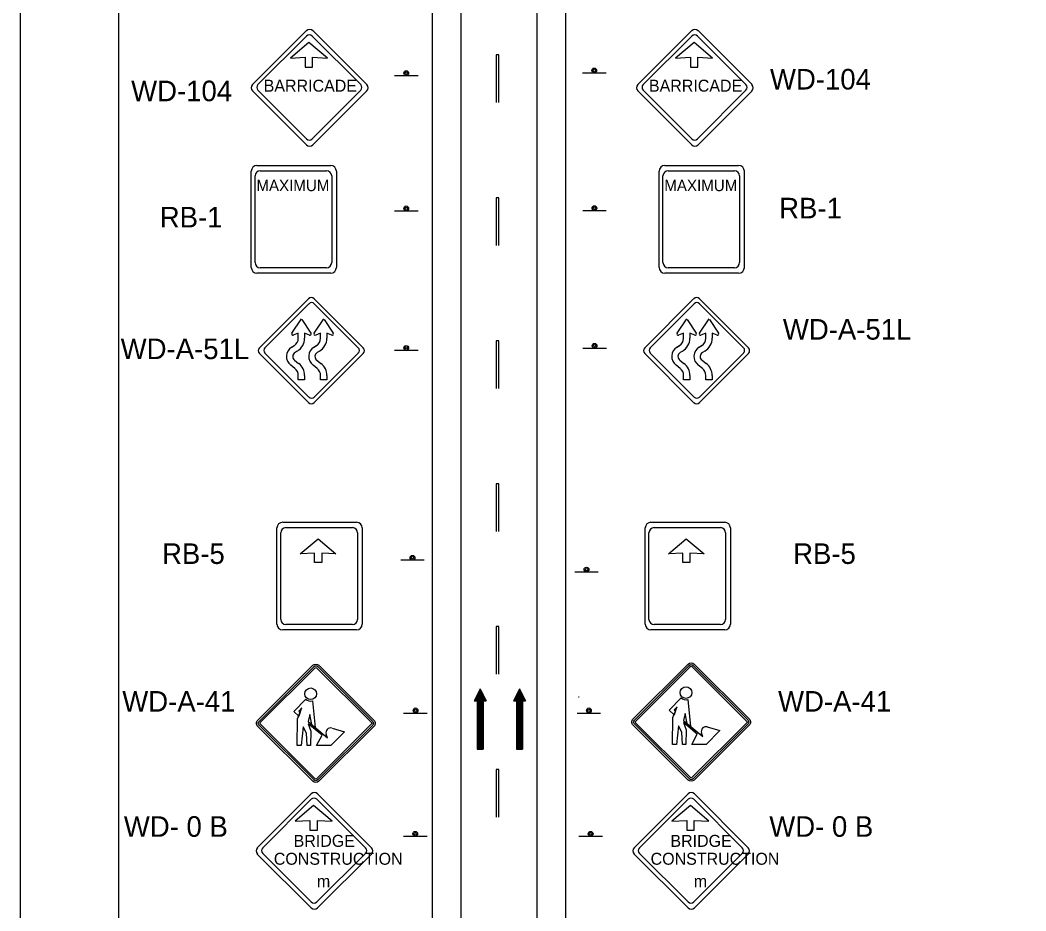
# Model space of a CAD drawing. Extents: x 2171 to 2395, y 134 to 413.
# Drawn here: x 2178.7 to 2280.9, y 183.7 to 274.1 of the extents above; entities that cross this region are included whole.
import ezdxf

# ---------------------------------------------------------------- set-up
doc = ezdxf.new("R2010")
doc.units = 0
for name, color, linetype in [('Level 1', 7, 'Continuous'), ('Level 10', 7, 'Continuous'), ('Level 2', 7, 'Continuous'), ('Level 20', 7, 'Continuous'), ('Level 44', 7, 'Continuous'), ('Level 60', 7, 'Continuous')]:
    doc.layers.add(name, color=color, linetype=linetype)

# ---------------------------------------------------------------- blocks, each defined once
blk = doc.blocks.new('2_95')
at = {"layer": 'Level 1'}
for points in [[(18.2, 120), (22.8, 116.1), (17.3, 102.4), (0, 118.7), (41.6, 161.6)], [(18.2, 120), (22.8, 116.1), (17.3, 102.4), (0, 118.7), (41.6, 161.6)], [(32.4, 65), (26.3, 0), (11.7, 0), (13.7, 93.4), (17.3, 102.4), (0, 118.7), (41.6, 161.6)], [(65.4, 155.5), (75, 62.5), (62.7, 72.8), (55.6, 107.4), (49.8, 83.3), (117.8, 27.3), (113.1, 39.4)], [(65.4, 155.5), (75, 62.5), (62.7, 72.8), (55.6, 107.4), (49.8, 83.3), (117.8, 27.3), (113.1, 39.4)], [(65.4, 155.5), (75, 62.5), (117.8, 27.3), (113.1, 39.4)], [(132.9, 60.9), (176.6, 47.8), (129.3, 0), (79.5, 0), (98.2, 36), (49.8, 75.6), (59.3, 50.4), (58.1, 0), (46.2, 0), (44, 43), (32.4, 65), (26.3, 0), (11.7, 0), (13.7, 93.4), (28.7, 130.9), (18.2, 120)], [(132.9, 60.9), (176.6, 47.8), (129.3, 0), (79.5, 0), (98.2, 36), (49.8, 75.6), (59.3, 50.4), (58.1, 0), (46.2, 0), (44, 43), (32.4, 65), (26.3, 0), (11.7, 0), (13.7, 93.4), (28.7, 130.9), (18.2, 120)], [(132.9, 60.9), (176.6, 47.8), (129.3, 0), (79.5, 0), (98.2, 36), (49.8, 75.6), (59.3, 50.4), (58.1, 0), (46.2, 0), (44, 43), (32.4, 65)]]:
    blk.add_lwpolyline(points, dxfattribs=at)
for points in [[(18.2, 120), (22.8, 116.1), (28.7, 130.9)], [(62.7, 72.7), (55.6, 107.4), (49.8, 83.3)]]:
    blk.add_lwpolyline(points, close=True, dxfattribs=at)
blk.add_circle((58.9, 179.8), 20.2, dxfattribs=at)
blk.add_circle((58.9, 179.8), 20.2, dxfattribs=at)
blk.add_circle((58.9, 179.8), 20.2, dxfattribs=at)
for centre, radius, start, end in [((58.9, 179.8), 25.1, 226.3135, 284.9576), ((58.9, 179.8), 25.1, 226.3135, 284.9576), ((58.9, 179.8), 25.1, 226.3135, 284.9576), ((128.2, 45.3), 16.3, 73.381, 201.0999), ((128.2, 45.3), 16.3, 73.381, 201.0999), ((128.2, 45.3), 16.3, 73.381, 201.0999)]:
    blk.add_arc(centre, radius, start, end, dxfattribs=at)
blk = doc.blocks.new('WDA41')
at = {"layer": 'Level 1'}
for p, q in [((-6.55, 0.35), (-0.35, 6.54)), ((-6.41, 0.21), (-0.21, 6.4)), ((-6.27, 0.07), (-0.08, 6.27)), ((0.07, 6.27), (6.27, 0.08)), ((0.21, 6.41), (6.41, 0.21)), ((0.35, 6.54), (6.54, 0.35)), ((0.29, 3.83), (0.3, 3.83)), ((-0.35, -6.54), (-6.55, -0.35)), ((-0.21, -6.4), (-6.41, -0.21)), ((-0.07, -6.27), (-6.27, -0.08)), ((6.27, -0.07), (0.08, -6.27)), ((6.41, -0.21), (0.21, -6.4)), ((6.55, -0.35), (0.35, -6.54))]:
    blk.add_line(p, q, dxfattribs=at)
for centre, radius, start, end in [((0, 6.19), 0.495, 45.0349, 135), ((0, 6.19), 0.3, 45.0349, 135), ((0, 6.19), 0.105, 45.0349, 135), ((-6.2, 0), 0.495, 135, 225.0349), ((-6.2, 0), 0.3, 135, 225.0349), ((-6.2, 0), 0.105, 135, 225.0349), ((6.2, 0), 0.105, 315, 45.035), ((6.2, 0), 0.3, 315, 45.035), ((6.2, 0), 0.495, 315, 45.035), ((0, -6.19), 0.495, 225.0348, 315), ((0, -6.19), 0.3, 225.0348, 315), ((0, -6.19), 0.105, 225.0348, 315)]:
    blk.add_arc(centre, radius, start, end, dxfattribs=at)
at = {"layer": 'Level 1', "xscale": 0.032498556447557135, "yscale": -0.032498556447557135, "rotation": 180}
blk.add_blockref('2_95', (2.5, -2.52), dxfattribs=at)

msp = doc.modelspace()

# ---------------------------------------------------------------- linework, layer by layer
at = {"layer": 'Level 10'}
for p, q in [((2223.52, 177.99), (2223.52, 287.5)), ((2231.26, 177.84), (2231.26, 284.77)), ((2206.34, 242.32), (2207.31, 243.78)), ((2207.35, 243.72), (2208.28, 242.32)), ((2208.6, 242.32), (2209.58, 243.78)), ((2209.62, 243.72), (2210.55, 242.32)), ((2245.46, 242.32), (2246.43, 243.78)), ((2246.47, 243.72), (2247.41, 242.32)), ((2247.72, 242.32), (2248.7, 243.78)), ((2248.74, 243.72), (2249.67, 242.32)), ((2206.99, 242.33), (2206.49, 242.13)), ((2206.99, 241.83), (2206.99, 242.33)), ((2208.13, 242.13), (2207.63, 242.33)), ((2207.63, 242.33), (2207.63, 241.83)), ((2209.26, 242.33), (2208.76, 242.13)), ((2209.26, 241.83), (2209.26, 242.33)), ((2210.4, 242.13), (2209.89, 242.33)), ((2209.89, 242.33), (2209.89, 241.83)), ((2246.11, 242.33), (2245.61, 242.13)), ((2246.11, 241.83), (2246.11, 242.33)), ((2247.25, 242.13), (2246.75, 242.33)), ((2246.75, 242.33), (2246.75, 241.83)), ((2248.38, 242.33), (2247.88, 242.13)), ((2248.38, 241.83), (2248.38, 242.33)), ((2249.52, 242.13), (2249.01, 242.33)), ((2249.01, 242.33), (2249.01, 241.83)), ((2206.33, 240.93), (2206.56, 241.07)), ((2208.59, 240.93), (2208.82, 241.07)), ((2245.45, 240.93), (2245.68, 241.07)), ((2247.71, 240.93), (2247.94, 241.07)), ((2206.89, 240.52), (2206.66, 240.38)), ((2209.15, 240.52), (2208.92, 240.38)), ((2246.01, 240.52), (2245.78, 240.38)), ((2248.27, 240.52), (2248.04, 240.38)), ((2206.64, 238.76), (2206.23, 239.08)), ((2206.62, 239.58), (2207.03, 239.26)), ((2208.91, 238.76), (2208.49, 239.08)), ((2208.88, 239.58), (2209.29, 239.26)), ((2245.76, 238.76), (2245.35, 239.08)), ((2245.74, 239.58), (2246.15, 239.26)), ((2248.03, 238.76), (2247.61, 239.08)), ((2248, 239.58), (2248.41, 239.26)), ((2206.99, 237.59), (2206.99, 238.04)), ((2207.63, 238.04), (2207.63, 237.59)), ((2209.26, 237.59), (2209.26, 238.04)), ((2209.89, 238.04), (2209.89, 237.59)), ((2246.11, 237.59), (2246.11, 238.04)), ((2246.75, 238.04), (2246.75, 237.59)), ((2248.38, 237.59), (2248.38, 238.04)), ((2249.01, 238.04), (2249.01, 237.59)), ((2225.47, 206.23), (2224.85, 205)), ((2225.01, 205.31), (2225.01, 205)), ((2225.08, 205.46), (2225.08, 205)), ((2225.16, 205.62), (2225.16, 200.09)), ((2225.24, 205.77), (2225.24, 200.09)), ((2225.31, 205.92), (2225.31, 200.09)), ((2225.39, 206.08), (2225.39, 200.09)), ((2225.47, 206.23), (2225.47, 200.09)), ((2225.47, 206.23), (2226.08, 205)), ((2225.54, 206.08), (2225.54, 200.09)), ((2225.62, 205.92), (2225.62, 200.09)), ((2225.7, 205.77), (2225.7, 200.09)), ((2225.77, 205.62), (2225.77, 200.09)), ((2225.85, 205.46), (2225.85, 205)), ((2225.93, 205.31), (2225.93, 205)), ((2229.45, 206.23), (2228.84, 205)), ((2228.99, 205.31), (2228.99, 205)), ((2229.07, 205.46), (2229.07, 205)), ((2229.14, 205.62), (2229.14, 200.09)), ((2229.22, 205.77), (2229.22, 200.09)), ((2229.3, 205.92), (2229.3, 200.09)), ((2229.38, 206.08), (2229.38, 200.09)), ((2229.45, 206.23), (2229.45, 200.09)), ((2229.45, 206.23), (2230.06, 205)), ((2229.53, 206.08), (2229.53, 200.09)), ((2229.6, 205.92), (2229.6, 200.09)), ((2229.68, 205.77), (2229.68, 200.09)), ((2229.76, 205.62), (2229.76, 200.09)), ((2229.83, 205.46), (2229.83, 205)), ((2229.91, 205.31), (2229.91, 205)), ((2224.85, 205), (2225.16, 205)), ((2224.93, 205.16), (2224.93, 205)), ((2225.16, 205), (2225.16, 200.09)), ((2225.77, 205), (2225.77, 200.09)), ((2225.77, 205), (2226.08, 205)), ((2226, 205.16), (2226, 205)), ((2228.84, 205), (2229.14, 205)), ((2228.91, 205.16), (2228.91, 205)), ((2229.14, 205), (2229.14, 200.09)), ((2229.76, 205), (2229.76, 200.09)), ((2229.76, 205), (2230.06, 205)), ((2229.99, 205.16), (2229.99, 205)), ((2225.16, 200.09), (2225.77, 200.09)), ((2229.14, 200.09), (2229.76, 200.09))]:
    msp.add_line(p, q, dxfattribs=at)
for points in [[(2207.63, 237.59), (2206.99, 237.59)], [(2209.89, 237.59), (2209.26, 237.59)], [(2246.75, 237.59), (2246.11, 237.59)], [(2249.01, 237.59), (2248.38, 237.59)]]:
    msp.add_lwpolyline(points, dxfattribs=at)
for centre, radius, start, end in [((2206.45, 242.25), 0.128, 146.2788, 291.7539), ((2208.18, 242.25), 0.128, 248.2461, 33.7212), ((2208.71, 242.25), 0.128, 146.2788, 291.7539), ((2210.44, 242.25), 0.128, 248.2461, 33.7212), ((2245.57, 242.25), 0.128, 146.2788, 291.7539), ((2247.3, 242.25), 0.128, 248.2461, 33.7212), ((2247.83, 242.25), 0.128, 146.2788, 291.7539), ((2249.56, 242.25), 0.128, 248.2461, 33.7212), ((2206.1, 241.83), 0.897, 301.2095, 0), ((2206.1, 241.83), 1.54, 301.2095, 0), ((2208.36, 241.83), 0.897, 301.2095, 0), ((2208.36, 241.83), 1.54, 301.2095, 0), ((2245.22, 241.83), 0.897, 301.2095, 0), ((2245.22, 241.83), 1.54, 301.2095, 0), ((2247.48, 241.83), 0.897, 301.2095, 0), ((2247.48, 241.83), 1.54, 301.2095, 0), ((2206.91, 239.97), 1.12, 121.1816, 232.5768), ((2206.91, 239.97), 0.483, 121.1644, 232.5768), ((2209.17, 239.97), 1.12, 121.1816, 232.5768), ((2209.17, 239.97), 0.483, 121.1644, 232.5768), ((2246.03, 239.97), 1.12, 121.1816, 232.5768), ((2246.03, 239.97), 0.483, 121.1644, 232.5768), ((2248.29, 239.97), 1.12, 121.1816, 232.5768), ((2248.29, 239.97), 0.483, 121.1644, 232.5768), ((2206.1, 238.04), 1.54, 0, 52.5572), ((2208.36, 238.04), 1.54, 0, 52.5572), ((2245.22, 238.04), 1.54, 0, 52.5572), ((2247.48, 238.04), 1.54, 0, 52.5572), ((2206.1, 238.04), 0.897, 0, 52.5572), ((2208.36, 238.04), 0.897, 0, 52.5572), ((2245.22, 238.04), 0.897, 0, 52.5572), ((2247.48, 238.04), 0.897, 0, 52.5572)]:
    msp.add_arc(centre, radius, start, end, dxfattribs=at)
at = {"layer": 'Level 2'}
for p, q in [((2227.07, 270.59), (2227.07, 265.75)), ((2227.36, 270.59), (2227.07, 270.59)), ((2227.36, 265.75), (2227.36, 270.59)), ((2227.07, 256.07), (2227.07, 251.24)), ((2227.36, 256.07), (2227.07, 256.07)), ((2227.36, 251.24), (2227.36, 256.07)), ((2227.07, 241.56), (2227.07, 236.72)), ((2227.36, 241.56), (2227.07, 241.56)), ((2227.36, 236.72), (2227.36, 241.56)), ((2227.07, 227.05), (2227.07, 222.21)), ((2227.36, 227.05), (2227.07, 227.05)), ((2227.36, 222.21), (2227.36, 227.05)), ((2227.07, 212.53), (2227.07, 207.69)), ((2227.36, 212.53), (2227.07, 212.53)), ((2227.36, 207.69), (2227.36, 212.53)), ((2227.07, 198.02), (2227.07, 193.18)), ((2227.36, 198.02), (2227.07, 198.02)), ((2227.36, 193.18), (2227.36, 198.02))]:
    msp.add_line(p, q, dxfattribs=at)
at = {"layer": 'Level 20'}
for p, q in [((2234.16, 177.84), (2234.16, 327.61)), ((2220.62, 177.82), (2220.62, 313.63))]:
    msp.add_line(p, q, dxfattribs=at)
at = {"layer": 'Level 44'}
for p, q in [((2207.83, 273.06), (2202.35, 267.59)), ((2213.95, 267.59), (2208.48, 273.06)), ((2246.95, 273.06), (2241.47, 267.59)), ((2253.07, 267.59), (2247.6, 273.06)), ((2202.9, 267.58), (2207.83, 272.5)), ((2208.07, 271.86), (2206.19, 270.27)), ((2209.95, 270.27), (2208.07, 271.86)), ((2208.41, 272.5), (2213.34, 267.58)), ((2242.02, 267.58), (2246.95, 272.5)), ((2247.19, 271.86), (2245.31, 270.27)), ((2249.07, 270.27), (2247.19, 271.86)), ((2247.53, 272.5), (2252.45, 267.58)), ((2206.19, 270.27), (2207.69, 270.35)), ((2207.69, 270.35), (2207.69, 269.35)), ((2208.45, 269.35), (2208.45, 270.35)), ((2208.45, 270.35), (2209.95, 270.27)), ((2245.31, 270.27), (2246.81, 270.35)), ((2246.81, 270.35), (2246.81, 269.35)), ((2247.57, 269.35), (2247.57, 270.35)), ((2247.57, 270.35), (2249.07, 270.27)), ((2207.69, 269.35), (2208.44, 269.35)), ((2238.24, 268.74), (2235.84, 268.74)), ((2246.81, 269.35), (2247.56, 269.35)), ((2219.15, 268.47), (2216.76, 268.47)), ((2202.35, 266.94), (2207.83, 261.46)), ((2202.36, 266.94), (2202.35, 266.94)), ((2207.83, 262.07), (2202.9, 267)), ((2213.34, 267), (2208.41, 262.07)), ((2208.48, 261.46), (2213.95, 266.94)), ((2241.47, 266.94), (2246.95, 261.46)), ((2241.47, 266.94), (2241.47, 266.94)), ((2246.95, 262.07), (2242.02, 267)), ((2252.45, 267), (2247.53, 262.07)), ((2247.6, 261.46), (2253.07, 266.94)), ((2202.22, 249.01), (2202.22, 258.78)), ((2202.8, 259.36), (2210.29, 259.36)), ((2203.12, 258.82), (2209.87, 258.82)), ((2210.87, 258.78), (2210.87, 249.01)), ((2243.63, 249.01), (2243.63, 258.78)), ((2244.21, 259.36), (2251.71, 259.36)), ((2244.54, 258.82), (2251.28, 258.82)), ((2252.28, 258.78), (2252.28, 249.01)), ((2202.6, 249.5), (2202.6, 258.3)), ((2210.39, 258.3), (2210.39, 249.5)), ((2244.02, 249.5), (2244.02, 258.3)), ((2251.8, 258.3), (2251.8, 249.5)), ((2219.15, 254.74), (2216.76, 254.74)), ((2238.26, 254.76), (2235.87, 254.76)), ((2202.6, 249.5), (2202.6, 249.5)), ((2244.02, 249.5), (2244.02, 249.5)), ((2202.22, 249.01), (2202.22, 249.01)), ((2210.29, 248.43), (2202.8, 248.43)), ((2209.87, 248.98), (2203.12, 248.98)), ((2243.63, 249.01), (2243.63, 249.01)), ((2251.71, 248.43), (2244.21, 248.43)), ((2251.28, 248.98), (2244.54, 248.98)), ((2203.05, 240.86), (2208.02, 245.83)), ((2208.08, 245.33), (2203.6, 240.85)), ((2208.61, 245.83), (2213.59, 240.86)), ((2213.09, 240.85), (2208.61, 245.33)), ((2242.17, 240.86), (2247.14, 245.83)), ((2247.2, 245.33), (2242.72, 240.85)), ((2247.73, 245.83), (2252.71, 240.86)), ((2252.21, 240.85), (2247.73, 245.33)), ((2208.02, 235.29), (2203.05, 240.27)), ((2203.6, 240.32), (2208.08, 235.84)), ((2208.61, 235.84), (2213.09, 240.32)), ((2213.59, 240.27), (2208.61, 235.29)), ((2213.59, 240.27), (2213.59, 240.27)), ((2219.15, 240.56), (2216.76, 240.56)), ((2238.29, 240.78), (2235.89, 240.78)), ((2247.14, 235.29), (2242.17, 240.27)), ((2242.72, 240.32), (2247.2, 235.84)), ((2247.73, 235.84), (2252.21, 240.32)), ((2252.71, 240.27), (2247.73, 235.29)), ((2252.7, 240.27), (2252.71, 240.27)), ((2205.41, 223.13), (2212.91, 223.13)), ((2242.79, 223.13), (2250.29, 223.13)), ((2204.83, 212.78), (2204.83, 222.55)), ((2205.22, 213.27), (2205.22, 222.07)), ((2205.74, 222.59), (2212.49, 222.59)), ((2213.01, 222.07), (2213.01, 213.27)), ((2213.49, 222.55), (2213.49, 212.78)), ((2242.22, 212.78), (2242.22, 222.55)), ((2242.6, 213.27), (2242.6, 222.07)), ((2243.12, 222.59), (2249.87, 222.59)), ((2250.39, 222.07), (2250.39, 213.27)), ((2250.87, 222.55), (2250.87, 212.78)), ((2219.79, 219.27), (2217.4, 219.27)), ((2237.46, 218.07), (2235.07, 218.07)), ((2204.83, 212.78), (2204.83, 212.78)), ((2205.22, 213.27), (2205.22, 213.27)), ((2212.49, 212.75), (2205.74, 212.75)), ((2242.22, 212.78), (2242.22, 212.78)), ((2242.6, 213.27), (2242.6, 213.27)), ((2249.87, 212.75), (2243.12, 212.75)), ((2212.91, 212.2), (2205.41, 212.2)), ((2250.29, 212.2), (2242.79, 212.2)), ((2235.52, 205.38), (2235.43, 205.38)), ((2217.69, 203.76), (2220.09, 203.76)), ((2235.3, 203.76), (2237.69, 203.76)), ((2208.31, 195.55), (2202.83, 190.08)), ((2214.43, 190.08), (2208.96, 195.55)), ((2246.57, 195.55), (2241.09, 190.08)), ((2252.68, 190.08), (2247.21, 195.55)), ((2203.38, 190.08), (2208.31, 195)), ((2208.55, 194.36), (2206.67, 192.77)), ((2210.43, 192.77), (2208.55, 194.36)), ((2208.89, 195), (2213.82, 190.08)), ((2241.64, 190.08), (2246.57, 195)), ((2246.81, 194.36), (2244.93, 192.77)), ((2248.69, 192.77), (2246.81, 194.36)), ((2247.15, 195), (2252.07, 190.08)), ((2206.67, 192.77), (2208.18, 192.85)), ((2208.18, 192.85), (2208.18, 191.85)), ((2208.93, 191.85), (2208.93, 192.85)), ((2208.93, 192.85), (2210.43, 192.77)), ((2244.93, 192.77), (2246.43, 192.85)), ((2246.43, 192.85), (2246.43, 191.85)), ((2247.19, 191.85), (2247.19, 192.85)), ((2247.19, 192.85), (2248.69, 192.77)), ((2208.18, 191.85), (2208.93, 191.85)), ((2220.07, 191.23), (2217.68, 191.23)), ((2237.89, 191.23), (2235.49, 191.23)), ((2246.43, 191.85), (2247.18, 191.85)), ((2202.83, 189.43), (2208.31, 183.96)), ((2202.84, 189.43), (2202.83, 189.43)), ((2208.31, 184.57), (2203.38, 189.49)), ((2213.82, 189.49), (2208.89, 184.57)), ((2208.96, 183.96), (2214.43, 189.43)), ((2241.09, 189.43), (2246.57, 183.96)), ((2241.09, 189.43), (2241.09, 189.43)), ((2246.57, 184.57), (2241.64, 189.49)), ((2252.07, 189.49), (2247.15, 184.57)), ((2247.21, 183.96), (2252.68, 189.43))]:
    msp.add_line(p, q, dxfattribs=at)
for points in [[(2207.2, 219.93), (2209.01, 221.46), (2210.82, 219.93), (2209.37, 220.01), (2209.37, 219.05), (2208.65, 219.05), (2208.65, 220.01)], [(2244.58, 219.93), (2246.39, 221.46), (2248.2, 219.93), (2246.76, 220.01), (2246.76, 219.05), (2246.03, 219.05), (2246.03, 220.01)]]:
    msp.add_lwpolyline(points, close=True, dxfattribs=at)
for centre, radius in [((2217.95, 268.74), 0.24), ((2217.95, 268.74), 0.12), ((2237.04, 269.01), 0.24), ((2237.04, 269.01), 0.12), ((2217.95, 255.01), 0.24), ((2217.95, 255.01), 0.12), ((2237.06, 255.03), 0.24), ((2237.06, 255.03), 0.12), ((2217.95, 240.83), 0.24), ((2237.08, 241.05), 0.24), ((2237.08, 241.05), 0.12), ((2217.95, 240.83), 0.12), ((2218.59, 219.53), 0.24), ((2218.59, 219.53), 0.12), ((2236.26, 218.33), 0.24), ((2236.26, 218.33), 0.12), ((2218.9, 204.03), 0.24), ((2236.5, 204.03), 0.24), ((2218.9, 204.03), 0.12), ((2236.5, 204.03), 0.12), ((2218.87, 191.49), 0.24), ((2218.87, 191.49), 0.12), ((2236.68, 191.49), 0.24), ((2236.68, 191.49), 0.12)]:
    msp.add_circle(centre, radius, dxfattribs=at)
for centre, radius, start, end in [((2208.15, 272.73), 0.458, 45, 135), ((2247.27, 272.73), 0.458, 45, 135), ((2208.12, 272.21), 0.412, 45, 135), ((2247.24, 272.21), 0.412, 45, 135), ((2202.68, 267.26), 0.458, 135, 225), ((2203.19, 267.29), 0.412, 135, 225), ((2213.04, 267.29), 0.412, 315, 45), ((2213.62, 267.26), 0.458, 315, 45), ((2241.8, 267.26), 0.458, 135, 225), ((2242.31, 267.29), 0.412, 135, 225), ((2252.16, 267.29), 0.412, 315, 45), ((2252.74, 267.26), 0.458, 315, 45), ((2208.12, 262.36), 0.412, 225, 315), ((2208.15, 261.79), 0.458, 225, 315), ((2247.24, 262.36), 0.412, 225, 315), ((2247.27, 261.79), 0.458, 225, 315), ((2202.8, 258.78), 0.578, 90, 180), ((2203.12, 258.3), 0.52, 90, 180), ((2209.87, 258.3), 0.52, 360, 90), ((2210.29, 258.78), 0.578, 360, 90), ((2244.21, 258.78), 0.578, 90, 180), ((2244.54, 258.3), 0.52, 90, 180), ((2251.28, 258.3), 0.52, 360, 90), ((2251.71, 258.78), 0.578, 360, 90), ((2203.12, 249.5), 0.52, 180, 270), ((2209.87, 249.5), 0.52, 270, 360), ((2244.54, 249.5), 0.52, 180, 270), ((2251.28, 249.5), 0.52, 270, 360), ((2202.8, 249.01), 0.578, 180, 270), ((2210.29, 249.01), 0.578, 270, 360), ((2244.21, 249.01), 0.578, 180, 270), ((2251.71, 249.01), 0.578, 270, 360), ((2208.32, 245.54), 0.416, 45, 135), ((2208.35, 245.06), 0.375, 45, 135), ((2247.44, 245.54), 0.416, 45, 135), ((2247.47, 245.06), 0.375, 45, 135), ((2203.34, 240.56), 0.416, 135, 225), ((2203.87, 240.59), 0.375, 135, 225), ((2212.82, 240.59), 0.375, 315, 45), ((2213.29, 240.56), 0.416, 315, 45), ((2242.46, 240.56), 0.416, 135, 225), ((2242.99, 240.59), 0.375, 135, 225), ((2251.94, 240.59), 0.375, 315, 45), ((2252.41, 240.56), 0.416, 315, 45), ((2208.32, 235.59), 0.416, 225, 315), ((2208.35, 236.11), 0.375, 225, 315), ((2247.44, 235.59), 0.416, 225, 315), ((2247.47, 236.11), 0.375, 225, 315), ((2205.41, 222.55), 0.578, 90, 180), ((2212.91, 222.55), 0.578, 360, 90), ((2242.8, 222.55), 0.578, 90, 180), ((2250.29, 222.55), 0.578, 360, 90), ((2205.74, 222.07), 0.52, 90, 180), ((2212.49, 222.07), 0.52, 360, 90), ((2243.12, 222.07), 0.52, 90, 180), ((2249.87, 222.07), 0.52, 360, 90), ((2205.41, 212.78), 0.578, 180, 270), ((2205.74, 213.27), 0.52, 180, 270), ((2212.49, 213.27), 0.52, 270, 360), ((2212.91, 212.78), 0.578, 270, 360), ((2242.8, 212.78), 0.578, 180, 270), ((2243.12, 213.27), 0.52, 180, 270), ((2249.87, 213.27), 0.52, 270, 360), ((2250.29, 212.78), 0.578, 270, 360), ((2208.63, 195.23), 0.458, 45, 135), ((2208.6, 194.71), 0.412, 45, 135), ((2246.89, 195.23), 0.458, 45, 135), ((2246.86, 194.71), 0.412, 45, 135), ((2203.16, 189.76), 0.458, 135, 225), ((2203.68, 189.79), 0.412, 135, 225), ((2213.53, 189.79), 0.412, 315, 45), ((2214.11, 189.76), 0.458, 315, 45), ((2241.42, 189.76), 0.458, 135, 225), ((2241.93, 189.79), 0.412, 135, 225), ((2251.78, 189.79), 0.412, 315, 45), ((2252.36, 189.76), 0.458, 315, 45), ((2208.6, 184.86), 0.412, 225, 315), ((2208.63, 184.29), 0.458, 225, 315), ((2246.86, 184.86), 0.412, 225, 315), ((2246.89, 184.29), 0.458, 225, 315)]:
    msp.add_arc(centre, radius, start, end, dxfattribs=at)
at = {"layer": 'Level 60'}
for points in [[(2394.75, 412.76), (2178.75, 412.76), (2178.75, 133.76), (2394.75, 133.76)], [(2375.62, 401.95), (2188.75, 401.95), (2188.75, 144.57), (2375.62, 144.57)]]:
    msp.add_lwpolyline(points, close=True, dxfattribs=at)

# ---------------------------------------------------------------- block references
at = {"layer": 'Level 1', "xscale": 0.9, "yscale": -0.9, "rotation": 180}
for p in [(2208.78, 202.72), (2246.89, 202.84)]:
    msp.add_blockref('WDA41', p, dxfattribs=at)

# ---------------------------------------------------------------- texts
at = {"layer": 'Level 10'}
for s, p in [('WD-104', (2254.89, 267.08)), ('WD-104', (2190.02, 265.89)), ('RB-1', (2255.82, 253.99)), ('RB-1', (2192.93, 253.07)), ('WD-A-51L', (2256.2, 241.68)), ('WD-A-51L', (2188.96, 239.7)), ('RB-5', (2193.16, 218.9)), ('RB-5', (2257.24, 218.9)), ('WD-A-41', (2189.12, 203.9)), ('WD-A-41', (2255.71, 203.9)), ('WD- 0 B', (2189.28, 191.19)), ('WD- 0 B', (2254.82, 191.19))]:
    msp.add_text(s, height=2.09, dxfattribs=at).set_placement(p)
at = {"layer": 'Level 44'}
for s, height, p in [('BARRICADE', 1.214, (2203.48, 266.86)), ('BARRICADE', 1.214, (2242.6, 266.86)), ('MAXIMUM', 1.147, (2202.74, 256.76)), ('MAXIMUM', 1.147, (2244.16, 256.76)), ('BRIDGE', 1.214, (2206.52, 190.17)), ('BRIDGE', 1.214, (2244.78, 190.17)), ('CONSTRUCTION', 1.214, (2204.51, 188.35)), ('CONSTRUCTION', 1.214, (2242.77, 188.35))]:
    msp.add_text(s, height=height, rotation=360, dxfattribs=at).set_placement(p)
for p in [(2208.89, 186.07), (2247.15, 186.07)]:
    msp.add_text('m', height=1.21, dxfattribs=at).set_placement(p)

doc.saveas('drawing.dxf')
